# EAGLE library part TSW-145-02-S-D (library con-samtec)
THROUGH-HOLE .025" SQ POST HEADER Source: Samtec TSW.pdf
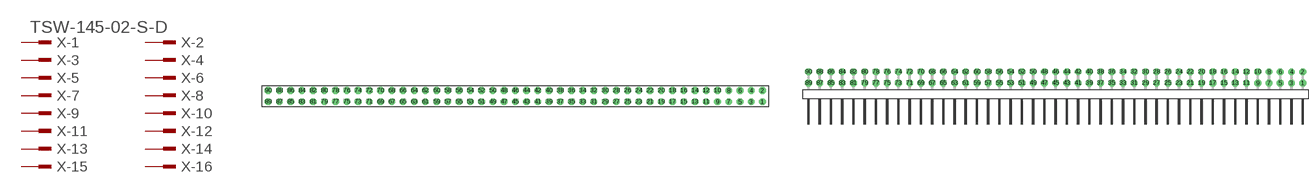
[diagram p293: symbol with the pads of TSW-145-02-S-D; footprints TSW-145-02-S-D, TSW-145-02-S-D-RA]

Designator prefix X; gates -1=MPINV -2=MPIN -3=MPIN -4=MPIN -5=MPIN -6=MPIN -7=MPIN -8=MPIN -9=MPIN -10=MPIN -11=MPIN -12=MPIN -13=MPIN -14=MPIN -15=MPIN -16=MPIN -17=MPIN -18=MPIN -19=MPIN -20=MPIN -21=MPIN -22=MPIN -23=MPIN -24=MPIN -25=MPIN -26=MPIN -27=MPIN -28=MPIN -29=MPIN -30=MPIN -31=MPIN -32=MPIN -33=MPIN -34=MPIN -35=MPIN -36=MPIN -37=MPIN -38=MPIN -39=MPIN -40=MPIN -41=MPIN -42=MPIN -43=MPIN -44=MPIN -45=MPIN -46=MPIN -47=MPIN -48=MPIN -49=MPIN -50=MPIN -51=MPIN -52=MPIN -53=MPIN -54=MPIN -55=MPIN -56=MPIN -57=MPIN -58=MPIN -59=MPIN -60=MPIN -61=MPIN -62=MPIN -63=MPIN -64=MPIN -65=MPIN -66=MPIN -67=MPIN -68=MPIN -69=MPIN -70=MPIN -71=MPIN -72=MPIN -73=MPIN -74=MPIN -75=MPIN -76=MPIN -77=MPIN -78=MPIN -79=MPIN -80=MPIN -81=MPIN -82=MPIN -83=MPIN -84=MPIN -85=MPIN -86=MPIN -87=MPIN -88=MPIN -89=MPIN -90=MPIN

## TSW-145-02-S-D (OC_FARNELL: unknown; OC_NEWARK: unknown)  [TSW-145-02-S-D]
1  -1:1  pas
2  -2:1  pas
3  -3:1  pas
4  -4:1  pas
5  -5:1  pas
6  -6:1  pas
7  -7:1  pas
8  -8:1  pas
9  -9:1  pas
10  -10:1  pas
11  -11:1  pas
12  -12:1  pas
13  -13:1  pas
14  -14:1  pas
15  -15:1  pas
16  -16:1  pas
17  -17:1  pas
18  -18:1  pas
19  -19:1  pas
20  -20:1  pas
21  -21:1  pas
22  -22:1  pas
23  -23:1  pas
24  -24:1  pas
25  -25:1  pas
26  -26:1  pas
27  -27:1  pas
28  -28:1  pas
29  -29:1  pas
30  -30:1  pas
31  -31:1  pas
32  -32:1  pas
33  -33:1  pas
34  -34:1  pas
35  -35:1  pas
36  -36:1  pas
37  -37:1  pas
38  -38:1  pas
39  -39:1  pas
40  -40:1  pas
41  -41:1  pas
42  -42:1  pas
43  -43:1  pas
44  -44:1  pas
45  -45:1  pas
46  -46:1  pas
47  -47:1  pas
48  -48:1  pas
49  -49:1  pas
50  -50:1  pas
51  -51:1  pas
52  -52:1  pas
53  -53:1  pas
54  -54:1  pas
55  -55:1  pas
56  -56:1  pas
57  -57:1  pas
58  -58:1  pas
59  -59:1  pas
60  -60:1  pas
61  -61:1  pas
62  -62:1  pas
63  -63:1  pas
64  -64:1  pas
65  -65:1  pas
66  -66:1  pas
67  -67:1  pas
68  -68:1  pas
69  -69:1  pas
70  -70:1  pas
71  -71:1  pas
72  -72:1  pas
73  -73:1  pas
74  -74:1  pas
75  -75:1  pas
76  -76:1  pas
77  -77:1  pas
78  -78:1  pas
79  -79:1  pas
80  -80:1  pas
81  -81:1  pas
82  -82:1  pas
83  -83:1  pas
84  -84:1  pas
85  -85:1  pas
86  -86:1  pas
87  -87:1  pas
88  -88:1  pas
89  -89:1  pas
90  -90:1  pas

## TSW-145-02-S-D-RA (OC_FARNELL: unknown; OC_NEWARK: unknown)  [TSW-145-02-S-D-RA]
Pads as for TSW-145-02-S-D

## Footprint TSW-145-02-S-D (pad centres in mm)
THROUGH-HOLE .025" SQ POST HEADER Source: Samtec TSW.pdf
drill 1 pad 1.5 octagon: 1 55.88,-1.27; 2 55.88,1.27; 3 53.34,-1.27; 4 53.34,1.27; 5 50.8,-1.27; 6 50.8,1.27; 7 48.26,-1.27; 8 48.26,1.27; 9 45.72,-1.27; 10 45.72,1.27; 11 43.18,-1.27; 12 43.18,1.27; 13 40.64,-1.27; 14 40.64,1.27; 15 38.1,-1.27; 16 38.1,1.27; 17 35.56,-1.27; 18 35.56,1.27; 19 33.02,-1.27; 20 33.02,1.27; 21 30.48,-1.27; 22 30.48,1.27; 23 27.94,-1.27; 24 27.94,1.27; 25 25.4,-1.27; 26 25.4,1.27; 27 22.86,-1.27; 28 22.86,1.27; 29 20.32,-1.27; 30 20.32,1.27; 31 17.78,-1.27; 32 17.78,1.27; 33 15.24,-1.27; 34 15.24,1.27; 35 12.7,-1.27; 36 12.7,1.27; 37 10.16,-1.27; 38 10.16,1.27; 39 7.62,-1.27; 40 7.62,1.27; 41 5.08,-1.27; 42 5.08,1.27; 43 2.54,-1.27; 44 2.54,1.27; 45 0,-1.27; 46 0,1.27; 47 -2.54,-1.27; 48 -2.54,1.27; 49 -5.08,-1.27; 50 -5.08,1.27; 51 -7.62,-1.27; 52 -7.62,1.27; 53 -10.16,-1.27; 54 -10.16,1.27; 55 -12.7,-1.27; 56 -12.7,1.27; 57 -15.24,-1.27; 58 -15.24,1.27; 59 -17.78,-1.27; 60 -17.78,1.27; 61 -20.32,-1.27; 62 -20.32,1.27; 63 -22.86,-1.27; 64 -22.86,1.27; 65 -25.4,-1.27; 66 -25.4,1.27; 67 -27.94,-1.27; 68 -27.94,1.27; 69 -30.48,-1.27; 70 -30.48,1.27; 71 -33.02,-1.27; 72 -33.02,1.27; 73 -35.56,-1.27; 74 -35.56,1.27; 75 -38.1,-1.27; 76 -38.1,1.27; 77 -40.64,-1.27; 78 -40.64,1.27; 79 -43.18,-1.27; 80 -43.18,1.27; 81 -45.72,-1.27; 82 -45.72,1.27; 83 -48.26,-1.27; 84 -48.26,1.27; 85 -50.8,-1.27; 86 -50.8,1.27; 87 -53.34,-1.27; 88 -53.34,1.27; 89 -55.88,-1.27; 90 -55.88,1.27

## Footprint TSW-145-02-S-D-RA (pad centres in mm)
THROUGH-HOLE .025" SQ POST HEADER Source: Samtec TSW.pdf
drill 1 pad 1.5 octagon: 1 55.88,1.524; 2 55.88,4.064; 3 53.34,1.524; 4 53.34,4.064; 5 50.8,1.524; 6 50.8,4.064; 7 48.26,1.524; 8 48.26,4.064; 9 45.72,1.524; 10 45.72,4.064; 11 43.18,1.524; 12 43.18,4.064; 13 40.64,1.524; 14 40.64,4.064; 15 38.1,1.524; 16 38.1,4.064; 17 35.56,1.524; 18 35.56,4.064; 19 33.02,1.524; 20 33.02,4.064; 21 30.48,1.524; 22 30.48,4.064; 23 27.94,1.524; 24 27.94,4.064; 25 25.4,1.524; 26 25.4,4.064; 27 22.86,1.524; 28 22.86,4.064; 29 20.32,1.524; 30 20.32,4.064; 31 17.78,1.524; 32 17.78,4.064; 33 15.24,1.524; 34 15.24,4.064; 35 12.7,1.524; 36 12.7,4.064; 37 10.16,1.524; 38 10.16,4.064; 39 7.62,1.524; 40 7.62,4.064; 41 5.08,1.524; 42 5.08,4.064; 43 2.54,1.524; 44 2.54,4.064; 45 0,1.524; 46 0,4.064; 47 -2.54,1.524; 48 -2.54,4.064; 49 -5.08,1.524; 50 -5.08,4.064; 51 -7.62,1.524; 52 -7.62,4.064; 53 -10.16,1.524; 54 -10.16,4.064; 55 -12.7,1.524; 56 -12.7,4.064; 57 -15.24,1.524; 58 -15.24,4.064; 59 -17.78,1.524; 60 -17.78,4.064; 61 -20.32,1.524; 62 -20.32,4.064; 63 -22.86,1.524; 64 -22.86,4.064; 65 -25.4,1.524; 66 -25.4,4.064; 67 -27.94,1.524; 68 -27.94,4.064; 69 -30.48,1.524; 70 -30.48,4.064; 71 -33.02,1.524; 72 -33.02,4.064; 73 -35.56,1.524; 74 -35.56,4.064; 75 -38.1,1.524; 76 -38.1,4.064; 77 -40.64,1.524; 78 -40.64,4.064; 79 -43.18,1.524; 80 -43.18,4.064; 81 -45.72,1.524; 82 -45.72,4.064; 83 -48.26,1.524; 84 -48.26,4.064; 85 -50.8,1.524; 86 -50.8,4.064; 87 -53.34,1.524; 88 -53.34,4.064; 89 -55.88,1.524; 90 -55.88,4.064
